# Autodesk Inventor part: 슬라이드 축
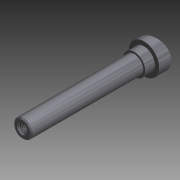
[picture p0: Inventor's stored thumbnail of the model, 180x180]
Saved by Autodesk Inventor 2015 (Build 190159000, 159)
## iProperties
Created: 2012-05
Part Number: 슬라이드 축
Document SubType Name: 모델링
Designer: SeoGD™
Mass: 169.348 g
Surface Area: 67.586 cm^2
Volume: 21.5729 cm^3
Density: 7.85 g/cm^3
Material: 강철, 연강
Appearance: 반연마
변환 표준: STEP AP214IS
파일 이름: C:\Users\SeoGD\Desktop\?쒗뿕\異?stp
전처리기: Build: 253, Release: 2010 SP1 - Date: Wed 07/29/2009
전송 단위: 밀리미터
불확실성: 0.01
Author: SeoGD™
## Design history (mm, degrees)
sketch "스케치1"
  geometry: L1 (0, 100)-(7.5, 100); L2 (7.5, 100)-(7.5, 0); L3 (7.5, 0)-(12.5, 0); L4 (12.5, 0)-(12.5, -17); L5 (12.5, -17)-(0, -17); L6 (0, -17)-(0, 100); 1 further point
  constraints: 12 end point, 2 parallel, 2 point on line, 1 perpendicular, 1 vertical
  dimensions: "d0" = 100 distance from line of L1 point (0, 0); "d1" = 15 diameter of L2 L6; "d2" = 25 diameter of L4 L6; "d3" = 17 distance of L3.end L4.end
revolve "회전1" sketch "스케치1" stored, may be unused: angle "d4" = 90 deg
sketch "스케치2"
  geometry: L1 (12.5, 0)-(12.5, -17) reference; L2 (-12.5, -17)-(12.5, -17) reference; L3 (-12.5, 0)-(-12.5, -17) reference; L4 (12.5, -5)-(-12.5, -11.699); L5 (-12.5, 0)-(12.5, 0) reference; 1 further point
  constraints: 2 end point, 2 point on line
  dimensions: "d5" = 75 deg angle of L1 L4; "d6" = 5 distance from line of L4.start L5
extrude "돌출1" cut sketch "스케치2" stored distance "d7" = 10; taper "d8" = 0 deg
chamfer "모따기1" distance "d9" = 1; stored, may be unused: second distance "d10" = 2, angle "d11" = 45 deg
fillet "모깎기1" dims "d12" = 0.5
hole "구멍1" diameter "d15" = 6.647; stored, may be unused: countersink angle "d19" = 90 deg, drill point angle "d21" = 118 deg; dims "d13" = 10, "d14" = 10, "d16" = 17, "d17" = 4, "d18" = 2, "d20" = 20
chamfer "모따기2" distance "d22" = 1; stored, may be unused: second distance "d23" = 2, angle "d24" = 45 deg
sketch "스케치3"
  geometry: C1 r 9 at (0, 0); 1 further point
  constraints: 1 centre point, 1 coincident
  dimensions: "d25" = 18 diameter of C1
extrude "돌출2" join sketch "스케치3" distance "d26" = 8; taper "d27" = 0 deg
node "솔리드1"
node "솔리드 본체"
node "곡면 본체"
node "솔리드2"
